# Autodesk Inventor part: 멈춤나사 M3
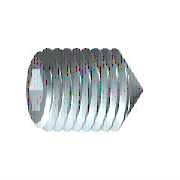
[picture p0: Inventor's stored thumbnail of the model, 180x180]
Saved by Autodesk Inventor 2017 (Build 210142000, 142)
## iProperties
Created: 2012-02
Part Number: 멈춤나사 M3
Material: 강철, 연강
Description: 6각 소켓 머리 없는 멈춤 나사
Document SubType Name: Modeling
Standard: KS B 1028
Designer: mduedu
Standards Organization: KS
Language: ko-KR
Size Designation: 원추점 M3x8
Categories: <MemberInstance><Categories><Category DisplayName="조임쇠" InternalName="e4da775c-781d-43d5-af7c-5136215cf5a6" Mnemonic="FSTN"><Category DisplayName="볼트" InternalN
Density: 7.86 g/cm^3
Mass: 0.360339 g
Surface Area: 0.888172 cm^2
Volume: 0.0458447 cm^3
Appearance: 노란색
IsCustomPart: 1
Author: mduedu
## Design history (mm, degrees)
sketch "스케치1"
  geometry: L1 (0, 0)-(5.5, 0); L2 (8, 0.866)-(8, 1.5); L3 (8, 1.5)-(0, 1.5); L4 (8, 0.866)-(6, 0.866); L5 (6, 0.866)-(5.5, 0); L6 (0, -0.3)-(0, 1.8) reference; L7 (0, 1.5)-(0, 0)
  constraints: 13 end point, 3 parallel, 1 collinear, 1 perpendicular, 1 point on line
  dimensions: "d0" = 2 distance of L2.start L4.end (= INTI); "d1" = 60 deg angle of L5 L1; "d2" = 3 diameter of L3 L1 (= NND); "d3" = 1.73205 diameter of L4 L1 (= 1.1547 x SW); "d5" = 8 distance from line of L2 L3.end (= NLG)
revolve "본체" sketch "스케치1" stored, may be unused: angle "d6" = 90 deg
sketch "스케치2"
  geometry: L1 (-0.433, 0.75)-(0.433, 0.75); L2 (0.433, 0.75)-(0.866, 0); L3 (0.866, 0)-(0.433, -0.75); L4 (0.433, -0.75)-(-0.433, -0.75); L5 (-0.433, -0.75)-(-0.866, 0); L6 (-0.866, 0)-(-0.433, 0.75); 3 further points
  constraints: 12 end point, 1 coincident, 1 horizontal, 13 other
extrude "슬롯" join sketch "스케치2" taper "d7" = 0 deg; stored distance "d21" = 10
workaxis "Work Axis1"
workplane "Work Plane1"
sketch "스케치5"
  geometry: L1 (-4, -0.15)-(-2.65, -1.5) reference; L2 (-4, 0.15)-(-2.65, 1.5) reference; L3 (-2.65, 1.5)-(-4.15, 0); L4 (-2.65, -1.5)-(-4.15, 0); 1 further point
  constraints: 4 end point, 1 horizontal alignment, 1 perpendicular
node "작업점1"
body "Solid1"
feature "스레드" dims "d12" = 8 (= NLG), "d13" = 0
chamfer "모따기1" distance "d8" = 1.35 (computed from NND, SPD, FAWI); stored, may be unused: angle "d9" = 45 deg (= FAWI), second distance "d34" = 1.35 (computed from NND, SPD, FAWI)
chamfer "모따기2" distance "d10" = 0.30673 (= -0.5 x GD1 + 0.5 x NND); stored, may be unused: angle "d11" = 45 deg (= FAWI), second distance "d35" = 0.30673 (= -0.5 x GD1 + 0.5 x NND)
other parameters: "NND" = 3 [user parameter; used in 5 equation terms], "NLG" = 8 [user parameter; used in 2 equation terms], "INTI" = 2 [user parameter; used in 1 equation term], "FAWI" = 45 deg [user parameter; used in 4 equation terms], "SW" = 1.5 [user parameter; used in 2 equation terms], "GD1" = 2.38655 (= THREADDIA - 1.2269 x PTC) [user parameter; used in 2 equation terms], "d4" = 0, "FAWI1" = 45 deg [user parameter], "SPD" = 0.3 [user parameter; used in 2 equation terms], "d36" = 0, "d37" = 0, "GUL" = 0.30673 (= 0.61345 x PTC) [user parameter], "TOA" = 30 deg [user parameter], "THREADDIA" = 3 [user parameter; used in 1 equation term], "PTC" = 0.5 [user parameter; used in 4 equation terms], "GAL" = 0.30673 (= 0.61345 x PTC) [user parameter], "E0" = 1.7325 (= 1.155 x SW) [user parameter]
